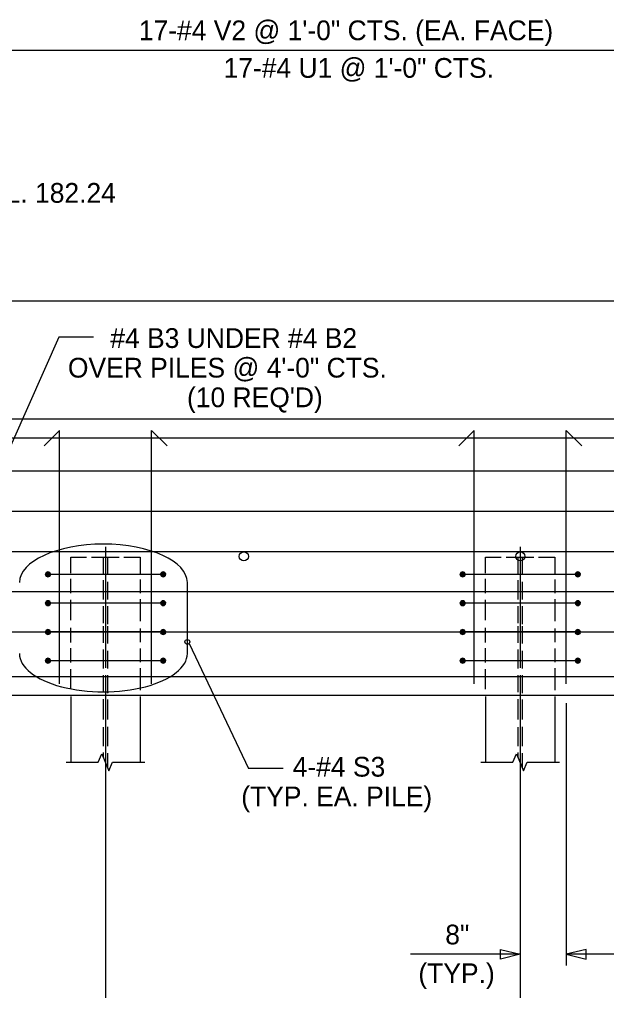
# Model space of a CAD drawing. Extents: x -41 to 251, y -169 to 237.
# Drawn here: x 19.8 to 28.3, y -40.84 to -26.78 of the extents above; entities that cross this region are included whole.
import ezdxf

# ---------------------------------------------------------------- set-up
doc = ezdxf.new("R2010")
doc.units = 0
for name, color, linetype in [('Arrowhead Terminators', 7, 'Continuous'), ('Arrowhead Terminators CELL', 7, 'Continuous'), ('Dimension Lines', 7, 'Continuous'), ('Dimension Lines CELL', 7, 'Continuous'), ('Mis Object Lines', 7, 'Continuous'), ('Mis Object Lines Hidden', 7, 'Continuous'), ('Rebar Lines', 7, 'Continuous'), ('Rebar Lines CELL', 7, 'Continuous'), ('Text', 7, 'Continuous')]:
    doc.layers.add(name, color=color, linetype=linetype)

msp = doc.modelspace()

# ---------------------------------------------------------------- linework, layer by layer
at = {"layer": 'Arrowhead Terminators'}
msp.add_lwpolyline([(28.001, -40.244), (27.715, -40.315), (28.001, -40.387)], close=True, dxfattribs=at)
at = {"layer": 'Arrowhead Terminators CELL'}
msp.add_lwpolyline([(27.048, -40.315), (26.762, -40.387), (26.762, -40.244)], close=True, dxfattribs=at)
at = {"layer": 'Dimension Lines'}
for p, q in [((17.132, -27.225), (33.049, -27.225)), ((20.372, -31.38), (19.049, -34.361)), ((20.872, -31.38), (20.372, -31.38)), ((22.232, -35.96), (22.232, -34.933)), ((22.258, -35.817), (23.117, -37.627)), ((21.049, -36.565), (21.049, -43.232)), ((27.049, -36.565), (27.049, -42.914)), ((27.715, -36.68), (27.715, -40.475)), ((23.617, -37.627), (23.117, -37.627)), ((27.048, -40.315), (25.461, -40.315)), ((32.382, -40.315), (27.715, -40.315))]:
    msp.add_line(p, q, dxfattribs=at)
for centre, start_param, end_param in [((21.017, -34.933), 3.141593, 6.283185), ((21.017, -35.96), 0, 3.141593)]:
    msp.add_ellipse(centre, major_axis=(-1.215, 0), ratio=0.457627, start_param=start_param, end_param=end_param, dxfattribs=at)
at = {"layer": 'Dimension Lines CELL'}
msp.add_circle((22.232, -35.793), 0.0353, dxfattribs=at)
at = {"layer": 'Mis Object Lines'}
for p, q in [((16.84, -30.857), (39.746, -30.857)), ((17.137, -36.565), (40.197, -36.565))]:
    msp.add_line(p, q, dxfattribs=at)
at = {"layer": 'Mis Object Lines Hidden'}
msp.add_line((13.549, -32.565), (52.549, -32.565), dxfattribs=at)
at = {"layer": 'Rebar Lines'}
for p, q in [((20.382, -32.732), (20.158, -32.956)), ((20.382, -36.399), (20.382, -32.732)), ((21.715, -36.399), (21.715, -32.732)), ((21.715, -32.732), (21.939, -32.956)), ((26.382, -32.732), (26.158, -32.956)), ((26.382, -36.399), (26.382, -32.732)), ((27.715, -36.399), (27.715, -32.732)), ((27.715, -32.732), (27.939, -32.956)), ((14.256, -32.836), (51.836, -32.836)), ((13.797, -33.315), (31.672, -33.315)), ((13.797, -33.899), (31.672, -33.899)), ((21.049, -34.414), (21.049, -36.17)), ((27.049, -34.414), (27.049, -36.17)), ((13.797, -34.482), (31.672, -34.482)), ((21.017, -34.808), (21.017, -34.565)), ((21.08, -34.814), (21.08, -34.565)), ((27.017, -34.808), (27.017, -34.565)), ((27.08, -34.814), (27.08, -34.565)), ((21.017, -35.18), (21.017, -34.901)), ((21.08, -35.18), (21.08, -34.924)), ((27.017, -35.18), (27.017, -34.901)), ((27.08, -35.18), (27.08, -34.924)), ((13.797, -35.065), (31.672, -35.065)), ((21.017, -35.522), (21.017, -35.273)), ((21.08, -35.534), (21.08, -35.273)), ((27.017, -35.522), (27.017, -35.273)), ((27.08, -35.534), (27.08, -35.273)), ((21.017, -35.808), (21.017, -35.565)), ((21.08, -35.814), (21.08, -35.565)), ((27.017, -35.808), (27.017, -35.565)), ((27.08, -35.814), (27.08, -35.565)), ((13.797, -35.649), (31.672, -35.649)), ((21.017, -36.18), (21.017, -35.901)), ((21.08, -36.18), (21.08, -35.924)), ((27.017, -36.18), (27.017, -35.901)), ((27.08, -36.18), (27.08, -35.924)), ((21.017, -36.522), (21.017, -36.273)), ((21.08, -36.534), (21.08, -36.273)), ((27.017, -36.522), (27.017, -36.273)), ((27.08, -36.534), (27.08, -36.273)), ((14.256, -36.294), (51.836, -36.294)), ((21.049, -36.275), (21.049, -36.565)), ((27.049, -36.275), (27.049, -36.565)), ((20.548, -36.582), (20.548, -37.534)), ((21.017, -36.917), (21.017, -36.621)), ((21.049, -36.635), (21.049, -37.841)), ((21.08, -36.917), (21.08, -36.627)), ((21.549, -36.582), (21.549, -37.534)), ((26.548, -36.582), (26.548, -37.534)), ((27.017, -36.917), (27.017, -36.621)), ((27.049, -36.635), (27.049, -37.841)), ((27.08, -36.917), (27.08, -36.627)), ((27.549, -36.582), (27.549, -37.534)), ((21.017, -37.301), (21.017, -37.028)), ((21.08, -37.301), (21.08, -37.022)), ((27.017, -37.301), (27.017, -37.028)), ((27.08, -37.301), (27.08, -37.022)), ((21.017, -37.469), (21.017, -37.394)), ((27.017, -37.469), (27.017, -37.394)), ((21.08, -37.618), (21.08, -37.405)), ((27.08, -37.618), (27.08, -37.405))]:
    msp.add_line(p, q, dxfattribs=at)
for points in [[(20.548, -34.799), (20.548, -34.565), (20.771, -34.565)], [(20.846, -34.565), (21.246, -34.565)], [(21.315, -34.565), (21.548, -34.565), (21.548, -34.812)], [(26.548, -34.799), (26.548, -34.565), (26.771, -34.565)], [(26.846, -34.565), (27.246, -34.565)], [(27.315, -34.565), (27.548, -34.565), (27.548, -34.812)], [(20.548, -35.089), (20.548, -34.882)], [(21.548, -34.888), (21.548, -35.086)], [(26.548, -35.089), (26.548, -34.882)], [(27.548, -34.888), (27.548, -35.086)], [(20.548, -35.477), (20.548, -35.185)], [(21.548, -35.172), (21.548, -35.493)], [(26.548, -35.477), (26.548, -35.185)], [(27.548, -35.172), (27.548, -35.493)], [(20.548, -35.799), (20.548, -35.591)], [(21.548, -35.597), (21.548, -35.796)], [(26.548, -35.799), (26.548, -35.591)], [(27.548, -35.597), (27.548, -35.796)], [(20.548, -36.089), (20.548, -35.882)], [(21.548, -35.888), (21.548, -36.086)], [(26.548, -36.089), (26.548, -35.882)], [(27.548, -35.888), (27.548, -36.086)], [(20.548, -36.477), (20.548, -36.185)], [(21.548, -36.172), (21.548, -36.493)], [(26.548, -36.477), (26.548, -36.185)], [(27.548, -36.172), (27.548, -36.493)], [(20.479, -37.535), (20.94, -37.535), (20.995, -37.415), (21.097, -37.66), (21.149, -37.535), (21.615, -37.535)], [(26.479, -37.535), (26.94, -37.535), (26.995, -37.415), (27.097, -37.66), (27.149, -37.535), (27.615, -37.535)]]:
    msp.add_lwpolyline(points, dxfattribs=at)
for centre in [(23.049, -34.554), (27.049, -34.554)]:
    msp.add_circle(centre, 0.066, dxfattribs=at)
at = {"layer": 'Rebar Lines CELL'}
for p, q in [((21.882, -34.815), (20.215, -34.815)), ((27.882, -34.815), (26.215, -34.815)), ((21.882, -35.232), (20.215, -35.232)), ((27.882, -35.232), (26.215, -35.232)), ((21.882, -35.649), (20.215, -35.649)), ((27.882, -35.649), (26.215, -35.649)), ((21.882, -36.065), (20.215, -36.065)), ((27.882, -36.065), (26.215, -36.065))]:
    msp.add_line(p, q, dxfattribs=at)
for points in [[(20.215, -34.78), (20.202, -34.783), (20.19, -34.79), (20.183, -34.802), (20.18, -34.815), (20.183, -34.829), (20.19, -34.84), (20.202, -34.848), (20.215, -34.851), (20.229, -34.848), (20.24, -34.84), (20.248, -34.829), (20.25, -34.815), (20.248, -34.802), (20.24, -34.79), (20.229, -34.783), (20.215, -34.78), (20.215, -34.815), (20.215, -34.851), (20.202, -34.848), (20.215, -34.815), (20.19, -34.84), (20.183, -34.829), (20.215, -34.815), (20.18, -34.815), (20.183, -34.802), (20.215, -34.815), (20.19, -34.79), (20.202, -34.783), (20.215, -34.815), (20.229, -34.783), (20.24, -34.79), (20.215, -34.815), (20.248, -34.802), (20.25, -34.815), (20.215, -34.815), (20.248, -34.829), (20.24, -34.84), (20.215, -34.815), (20.229, -34.848)], [(21.882, -34.78), (21.868, -34.783), (21.857, -34.79), (21.849, -34.802), (21.847, -34.815), (21.849, -34.829), (21.857, -34.84), (21.868, -34.848), (21.882, -34.851), (21.895, -34.848), (21.907, -34.84), (21.914, -34.829), (21.917, -34.815), (21.914, -34.802), (21.907, -34.79), (21.895, -34.783), (21.882, -34.78), (21.882, -34.815), (21.882, -34.851), (21.868, -34.848), (21.882, -34.815), (21.857, -34.84), (21.849, -34.829), (21.882, -34.815), (21.847, -34.815), (21.849, -34.802), (21.882, -34.815), (21.857, -34.79), (21.868, -34.783), (21.882, -34.815), (21.895, -34.783), (21.907, -34.79), (21.882, -34.815), (21.914, -34.802), (21.917, -34.815), (21.882, -34.815), (21.914, -34.829), (21.907, -34.84), (21.882, -34.815), (21.895, -34.848)], [(26.215, -34.78), (26.202, -34.783), (26.19, -34.79), (26.183, -34.802), (26.18, -34.815), (26.183, -34.829), (26.19, -34.84), (26.202, -34.848), (26.215, -34.851), (26.229, -34.848), (26.24, -34.84), (26.248, -34.829), (26.25, -34.815), (26.248, -34.802), (26.24, -34.79), (26.229, -34.783), (26.215, -34.78), (26.215, -34.815), (26.215, -34.851), (26.202, -34.848), (26.215, -34.815), (26.19, -34.84), (26.183, -34.829), (26.215, -34.815), (26.18, -34.815), (26.183, -34.802), (26.215, -34.815), (26.19, -34.79), (26.202, -34.783), (26.215, -34.815), (26.229, -34.783), (26.24, -34.79), (26.215, -34.815), (26.248, -34.802), (26.25, -34.815), (26.215, -34.815), (26.248, -34.829), (26.24, -34.84), (26.215, -34.815), (26.229, -34.848)], [(27.882, -34.78), (27.868, -34.783), (27.857, -34.79), (27.849, -34.802), (27.847, -34.815), (27.849, -34.829), (27.857, -34.84), (27.868, -34.848), (27.882, -34.851), (27.895, -34.848), (27.907, -34.84), (27.914, -34.829), (27.917, -34.815), (27.914, -34.802), (27.907, -34.79), (27.895, -34.783), (27.882, -34.78), (27.882, -34.815), (27.882, -34.851), (27.868, -34.848), (27.882, -34.815), (27.857, -34.84), (27.849, -34.829), (27.882, -34.815), (27.847, -34.815), (27.849, -34.802), (27.882, -34.815), (27.857, -34.79), (27.868, -34.783), (27.882, -34.815), (27.895, -34.783), (27.907, -34.79), (27.882, -34.815), (27.914, -34.802), (27.917, -34.815), (27.882, -34.815), (27.914, -34.829), (27.907, -34.84), (27.882, -34.815), (27.895, -34.848)], [(20.215, -35.197), (20.202, -35.199), (20.19, -35.207), (20.183, -35.218), (20.18, -35.232), (20.183, -35.245), (20.19, -35.257), (20.202, -35.264), (20.215, -35.267), (20.229, -35.264), (20.24, -35.257), (20.248, -35.245), (20.25, -35.232), (20.248, -35.218), (20.24, -35.207), (20.229, -35.199), (20.215, -35.197), (20.215, -35.232), (20.215, -35.267), (20.202, -35.264), (20.215, -35.232), (20.19, -35.257), (20.183, -35.245), (20.215, -35.232), (20.18, -35.232), (20.183, -35.218), (20.215, -35.232), (20.19, -35.207), (20.202, -35.199), (20.215, -35.232), (20.229, -35.199), (20.24, -35.207), (20.215, -35.232), (20.248, -35.218), (20.25, -35.232), (20.215, -35.232), (20.248, -35.245), (20.24, -35.257), (20.215, -35.232), (20.229, -35.264)], [(21.882, -35.197), (21.868, -35.199), (21.857, -35.207), (21.849, -35.218), (21.847, -35.232), (21.849, -35.245), (21.857, -35.257), (21.868, -35.264), (21.882, -35.267), (21.895, -35.264), (21.907, -35.257), (21.914, -35.245), (21.917, -35.232), (21.914, -35.218), (21.907, -35.207), (21.895, -35.199), (21.882, -35.197), (21.882, -35.232), (21.882, -35.267), (21.868, -35.264), (21.882, -35.232), (21.857, -35.257), (21.849, -35.245), (21.882, -35.232), (21.847, -35.232), (21.849, -35.218), (21.882, -35.232), (21.857, -35.207), (21.868, -35.199), (21.882, -35.232), (21.895, -35.199), (21.907, -35.207), (21.882, -35.232), (21.914, -35.218), (21.917, -35.232), (21.882, -35.232), (21.914, -35.245), (21.907, -35.257), (21.882, -35.232), (21.895, -35.264)], [(26.215, -35.197), (26.202, -35.199), (26.19, -35.207), (26.183, -35.218), (26.18, -35.232), (26.183, -35.245), (26.19, -35.257), (26.202, -35.264), (26.215, -35.267), (26.229, -35.264), (26.24, -35.257), (26.248, -35.245), (26.25, -35.232), (26.248, -35.218), (26.24, -35.207), (26.229, -35.199), (26.215, -35.197), (26.215, -35.232), (26.215, -35.267), (26.202, -35.264), (26.215, -35.232), (26.19, -35.257), (26.183, -35.245), (26.215, -35.232), (26.18, -35.232), (26.183, -35.218), (26.215, -35.232), (26.19, -35.207), (26.202, -35.199), (26.215, -35.232), (26.229, -35.199), (26.24, -35.207), (26.215, -35.232), (26.248, -35.218), (26.25, -35.232), (26.215, -35.232), (26.248, -35.245), (26.24, -35.257), (26.215, -35.232), (26.229, -35.264)], [(27.882, -35.197), (27.868, -35.199), (27.857, -35.207), (27.849, -35.218), (27.847, -35.232), (27.849, -35.245), (27.857, -35.257), (27.868, -35.264), (27.882, -35.267), (27.895, -35.264), (27.907, -35.257), (27.914, -35.245), (27.917, -35.232), (27.914, -35.218), (27.907, -35.207), (27.895, -35.199), (27.882, -35.197), (27.882, -35.232), (27.882, -35.267), (27.868, -35.264), (27.882, -35.232), (27.857, -35.257), (27.849, -35.245), (27.882, -35.232), (27.847, -35.232), (27.849, -35.218), (27.882, -35.232), (27.857, -35.207), (27.868, -35.199), (27.882, -35.232), (27.895, -35.199), (27.907, -35.207), (27.882, -35.232), (27.914, -35.218), (27.917, -35.232), (27.882, -35.232), (27.914, -35.245), (27.907, -35.257), (27.882, -35.232), (27.895, -35.264)], [(20.215, -35.613), (20.202, -35.616), (20.19, -35.624), (20.183, -35.635), (20.18, -35.649), (20.183, -35.662), (20.19, -35.674), (20.202, -35.681), (20.215, -35.684), (20.229, -35.681), (20.24, -35.674), (20.248, -35.662), (20.25, -35.649), (20.248, -35.635), (20.24, -35.624), (20.229, -35.616), (20.215, -35.613), (20.215, -35.649), (20.215, -35.684), (20.202, -35.681), (20.215, -35.649), (20.19, -35.674), (20.183, -35.662), (20.215, -35.649), (20.18, -35.649), (20.183, -35.635), (20.215, -35.649), (20.19, -35.624), (20.202, -35.616), (20.215, -35.649), (20.229, -35.616), (20.24, -35.624), (20.215, -35.649), (20.248, -35.635), (20.25, -35.649), (20.215, -35.649), (20.248, -35.662), (20.24, -35.674), (20.215, -35.649), (20.229, -35.681)], [(21.882, -35.613), (21.868, -35.616), (21.857, -35.624), (21.849, -35.635), (21.847, -35.649), (21.849, -35.662), (21.857, -35.674), (21.868, -35.681), (21.882, -35.684), (21.895, -35.681), (21.907, -35.674), (21.914, -35.662), (21.917, -35.649), (21.914, -35.635), (21.907, -35.624), (21.895, -35.616), (21.882, -35.613), (21.882, -35.649), (21.882, -35.684), (21.868, -35.681), (21.882, -35.649), (21.857, -35.674), (21.849, -35.662), (21.882, -35.649), (21.847, -35.649), (21.849, -35.635), (21.882, -35.649), (21.857, -35.624), (21.868, -35.616), (21.882, -35.649), (21.895, -35.616), (21.907, -35.624), (21.882, -35.649), (21.914, -35.635), (21.917, -35.649), (21.882, -35.649), (21.914, -35.662), (21.907, -35.674), (21.882, -35.649), (21.895, -35.681)], [(26.215, -35.613), (26.202, -35.616), (26.19, -35.624), (26.183, -35.635), (26.18, -35.649), (26.183, -35.662), (26.19, -35.674), (26.202, -35.681), (26.215, -35.684), (26.229, -35.681), (26.24, -35.674), (26.248, -35.662), (26.25, -35.649), (26.248, -35.635), (26.24, -35.624), (26.229, -35.616), (26.215, -35.613), (26.215, -35.649), (26.215, -35.684), (26.202, -35.681), (26.215, -35.649), (26.19, -35.674), (26.183, -35.662), (26.215, -35.649), (26.18, -35.649), (26.183, -35.635), (26.215, -35.649), (26.19, -35.624), (26.202, -35.616), (26.215, -35.649), (26.229, -35.616), (26.24, -35.624), (26.215, -35.649), (26.248, -35.635), (26.25, -35.649), (26.215, -35.649), (26.248, -35.662), (26.24, -35.674), (26.215, -35.649), (26.229, -35.681)], [(27.882, -35.613), (27.868, -35.616), (27.857, -35.624), (27.849, -35.635), (27.847, -35.649), (27.849, -35.662), (27.857, -35.674), (27.868, -35.681), (27.882, -35.684), (27.895, -35.681), (27.907, -35.674), (27.914, -35.662), (27.917, -35.649), (27.914, -35.635), (27.907, -35.624), (27.895, -35.616), (27.882, -35.613), (27.882, -35.649), (27.882, -35.684), (27.868, -35.681), (27.882, -35.649), (27.857, -35.674), (27.849, -35.662), (27.882, -35.649), (27.847, -35.649), (27.849, -35.635), (27.882, -35.649), (27.857, -35.624), (27.868, -35.616), (27.882, -35.649), (27.895, -35.616), (27.907, -35.624), (27.882, -35.649), (27.914, -35.635), (27.917, -35.649), (27.882, -35.649), (27.914, -35.662), (27.907, -35.674), (27.882, -35.649), (27.895, -35.681)], [(20.215, -36.03), (20.202, -36.033), (20.19, -36.04), (20.183, -36.052), (20.18, -36.065), (20.183, -36.079), (20.19, -36.09), (20.202, -36.098), (20.215, -36.101), (20.229, -36.098), (20.24, -36.09), (20.248, -36.079), (20.25, -36.065), (20.248, -36.052), (20.24, -36.04), (20.229, -36.033), (20.215, -36.03), (20.215, -36.065), (20.215, -36.101), (20.202, -36.098), (20.215, -36.065), (20.19, -36.09), (20.183, -36.079), (20.215, -36.065), (20.18, -36.065), (20.183, -36.052), (20.215, -36.065), (20.19, -36.04), (20.202, -36.033), (20.215, -36.065), (20.229, -36.033), (20.24, -36.04), (20.215, -36.065), (20.248, -36.052), (20.25, -36.065), (20.215, -36.065), (20.248, -36.079), (20.24, -36.09), (20.215, -36.065), (20.229, -36.098)], [(21.882, -36.03), (21.868, -36.033), (21.857, -36.04), (21.849, -36.052), (21.847, -36.065), (21.849, -36.079), (21.857, -36.09), (21.868, -36.098), (21.882, -36.101), (21.895, -36.098), (21.907, -36.09), (21.914, -36.079), (21.917, -36.065), (21.914, -36.052), (21.907, -36.04), (21.895, -36.033), (21.882, -36.03), (21.882, -36.065), (21.882, -36.101), (21.868, -36.098), (21.882, -36.065), (21.857, -36.09), (21.849, -36.079), (21.882, -36.065), (21.847, -36.065), (21.849, -36.052), (21.882, -36.065), (21.857, -36.04), (21.868, -36.033), (21.882, -36.065), (21.895, -36.033), (21.907, -36.04), (21.882, -36.065), (21.914, -36.052), (21.917, -36.065), (21.882, -36.065), (21.914, -36.079), (21.907, -36.09), (21.882, -36.065), (21.895, -36.098)], [(26.215, -36.03), (26.202, -36.033), (26.19, -36.04), (26.183, -36.052), (26.18, -36.065), (26.183, -36.079), (26.19, -36.09), (26.202, -36.098), (26.215, -36.101), (26.229, -36.098), (26.24, -36.09), (26.248, -36.079), (26.25, -36.065), (26.248, -36.052), (26.24, -36.04), (26.229, -36.033), (26.215, -36.03), (26.215, -36.065), (26.215, -36.101), (26.202, -36.098), (26.215, -36.065), (26.19, -36.09), (26.183, -36.079), (26.215, -36.065), (26.18, -36.065), (26.183, -36.052), (26.215, -36.065), (26.19, -36.04), (26.202, -36.033), (26.215, -36.065), (26.229, -36.033), (26.24, -36.04), (26.215, -36.065), (26.248, -36.052), (26.25, -36.065), (26.215, -36.065), (26.248, -36.079), (26.24, -36.09), (26.215, -36.065), (26.229, -36.098)], [(27.882, -36.03), (27.868, -36.033), (27.857, -36.04), (27.849, -36.052), (27.847, -36.065), (27.849, -36.079), (27.857, -36.09), (27.868, -36.098), (27.882, -36.101), (27.895, -36.098), (27.907, -36.09), (27.914, -36.079), (27.917, -36.065), (27.914, -36.052), (27.907, -36.04), (27.895, -36.033), (27.882, -36.03), (27.882, -36.065), (27.882, -36.101), (27.868, -36.098), (27.882, -36.065), (27.857, -36.09), (27.849, -36.079), (27.882, -36.065), (27.847, -36.065), (27.849, -36.052), (27.882, -36.065), (27.857, -36.04), (27.868, -36.033), (27.882, -36.065), (27.895, -36.033), (27.907, -36.04), (27.882, -36.065), (27.914, -36.052), (27.917, -36.065), (27.882, -36.065), (27.914, -36.079), (27.907, -36.09), (27.882, -36.065), (27.895, -36.098)]]:
    msp.add_lwpolyline(points, dxfattribs=at)

# ---------------------------------------------------------------- texts
at = {"layer": 'Text'}
for s, p in [('17-#4 V2 @ 1\'-0" CTS. (EA. FACE)', (21.53, -27.082)), ('17-#4 U1 @ 1\'-0" CTS.', (22.756, -27.626)), ('EL. 182.24', (19.348, -29.435)), ('#4 B3 UNDER #4 B2', (21.117, -31.537)), ('OVER PILES @ 4\'-0" CTS.', (20.504, -31.966)), ("(10 REQ'D)", (22.227, -32.395)), ('4-#4 S3', (23.756, -37.743)), ('(TYP. EA. PILE)', (23.012, -38.172)), ('8"', (25.964, -40.172)), ('(TYP.)', (25.575, -40.733))]:
    msp.add_text(s, height=0.286, dxfattribs=at).set_placement(p)

doc.saveas('drawing.dxf')
